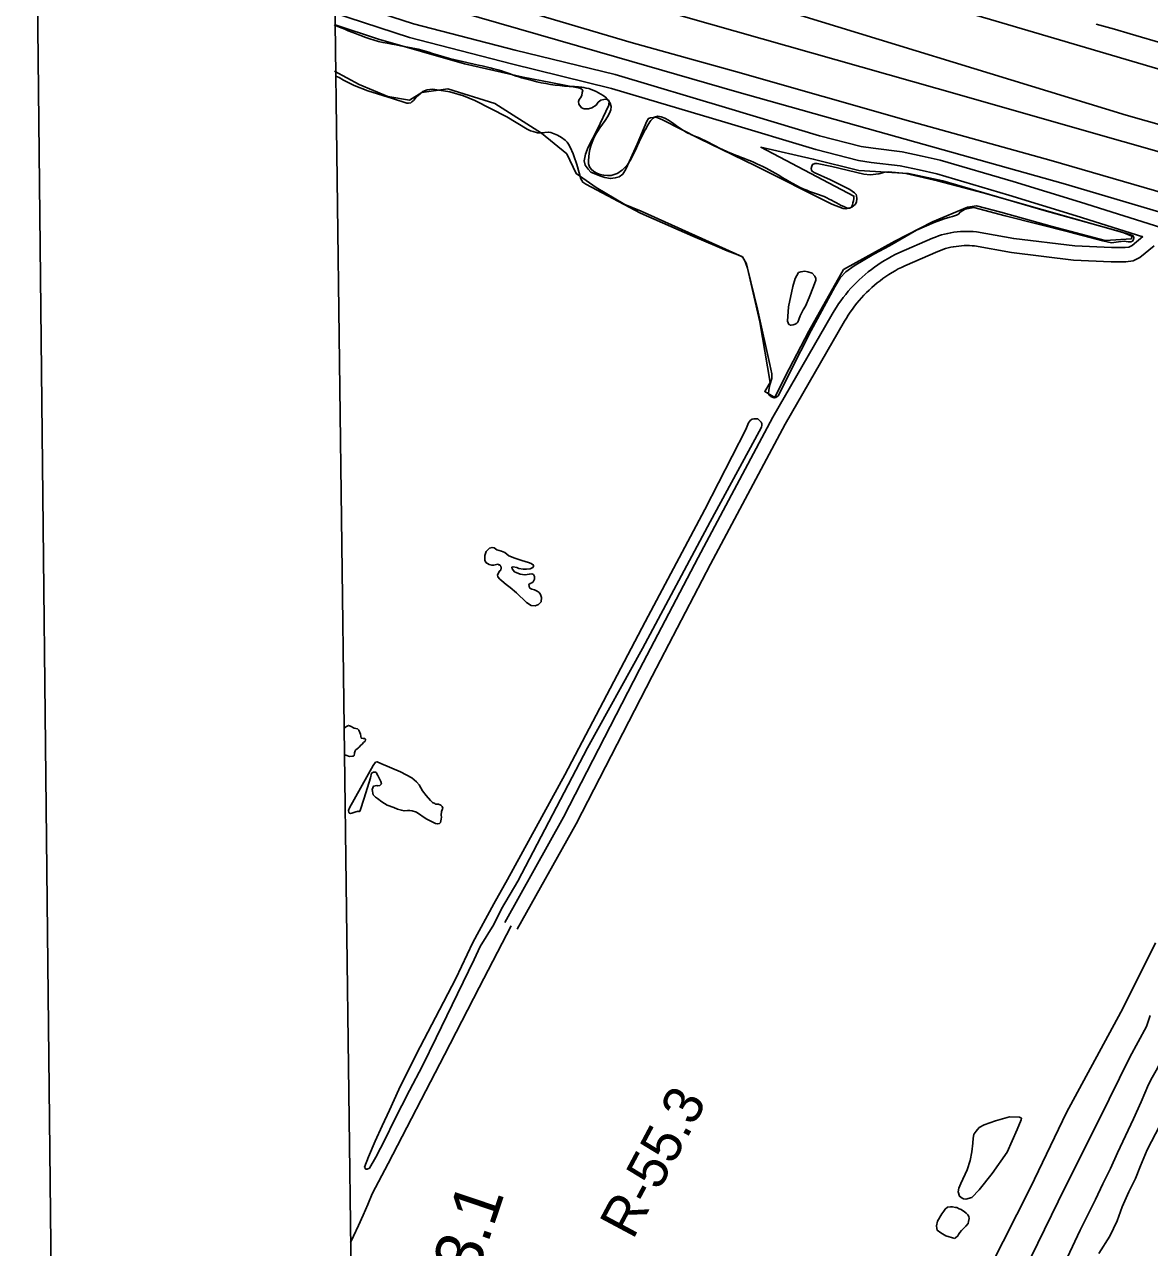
# Model space of a CAD drawing. Extents: x 3734862 to 3772949, y 391520 to 417239.
# Drawn here: x 3738202 to 3740576, y 410402 to 412981 of the extents above; entities that cross this region are included whole.
import ezdxf

# ---------------------------------------------------------------- set-up
doc = ezdxf.new("R2010")
doc.units = 0
for name, color, linetype in [('V-ANNO-SYMB', 7, 'Continuous'), ('V-GRID-FRAM', 7, 'Continuous'), ('V-LEVE-TOET', 7, 'Continuous'), ('V-RIVR-RANG-IDEN', 7, 'Continuous'), ('V-ROAD-CNTR', 7, 'Continuous'), ('V-SITE-VEGE', 7, 'Continuous'), ('V-SURV-IDEN', 7, 'Continuous'), ('V-TOPO-SHOR', 7, 'Continuous'), ('V-WETL-SWMP', 7, 'Continuous')]:
    doc.layers.add(name, color=color, linetype=linetype)

msp = doc.modelspace()

# ---------------------------------------------------------------- linework, layer by layer
at = {"layer": 'V-ANNO-SYMB'}
msp.add_lwpolyline([(3738444.4, 392757.5), (3771525.7, 393106.9), (3771283.7, 416022.2), (3738202.3, 415672.8), (3738444.4, 392757.5)], dxfattribs=at)
at = {"layer": 'V-GRID-FRAM'}
msp.add_lwpolyline([(3738832.3, 415033.8), (3770599.2, 415447.4), (3770843.8, 397266.6), (3739061.1, 396852.8), (3738832.3, 415033.8)], dxfattribs=at)
at = {"layer": 'V-LEVE-TOET'}
for points in [[(3738852.9, 413396.4), (3739138.4, 413315.6), (3740264.7, 412984.9), (3741306.9, 412677.6), (3741416.7, 412646.4), (3741439.2, 412637.7), (3741731.3, 412522.7), (3742578.6, 412200.2), (3743221.3, 411958.2), (3743367.5, 411908.1)], [(3744926.8, 411188.3), (3744890.4, 411207.3), (3744850.8, 411205.9), (3744810.7, 411224.9), (3744044.1, 411535), (3743485.6, 411757.3), (3743467, 411746.5), (3743430.2, 411739.8), (3743419.1, 411736.3), (3743236.4, 411801.8), (3743192.8, 411831.9), (3743145.7, 411873.1), (3742641.7, 412061.3), (3741586.5, 412475.4), (3741466, 412517.8), (3741404.7, 412536.6), (3741298.7, 412571.4), (3740527, 412789.8), (3739719, 413038.2), (3738899.6, 413268.3), (3738854.4, 413281.1)]]:
    msp.add_lwpolyline(points, dxfattribs=at)
at = {"layer": 'V-ROAD-CNTR'}
for points in [[(3738852, 413216.3), (3739597.6, 412997), (3740128.2, 412846.1), (3740911.5, 412622.8), (3741371.7, 412476), (3742051.4, 412232), (3742605.7, 412017.1), (3743130.7, 411814.9), (3743608.3, 411634.1), (3744107.4, 411440.8)], [(3738862.3, 413035.2), (3739023, 412982.8), (3739237.4, 412927.1), (3739448.5, 412875.5), (3739688.3, 412804.2), (3739880, 412746.4), (3739967.9, 412724.2), (3739993.1, 412720.2), (3740054.5, 412712.6), (3740096.2, 412703.8), (3740134.5, 412695.2), (3740288, 412650), (3740430.4, 412606.5), (3740613.5, 412548.9), (3740830.5, 412486.5), (3741011.5, 412434), (3741254.2, 412360.8), (3741297.7, 412344.9), (3741301, 412343.4), (3741304.5, 412341.7), (3741307.8, 412339.7), (3741310.9, 412337.4), (3741314.4, 412334.5), (3741315.1, 412333.7)], [(3738853, 413006.7), (3739014.6, 412954), (3739230.1, 412898), (3739440.6, 412846.5), (3739679.7, 412775.4), (3739872, 412717.5), (3739961.9, 412694.8), (3739988.9, 412690.5), (3740049.6, 412683), (3740089.8, 412674.5), (3740127, 412666.1), (3740279.4, 412621.3), (3740421.6, 412577.9), (3740562, 412533.7)], [(3739215.9, 411087.9), (3739339.5, 411310), (3739500.1, 411621.1), (3739623.6, 411857), (3739781.4, 412153.3), (3739906.6, 412370.7), (3739910.8, 412377.8), (3739915.3, 412385), (3739920, 412392), (3739924.8, 412398.8), (3739929.9, 412405.6), (3739935.1, 412412.2), (3739940.5, 412418.7), (3739946, 412425), (3739951.7, 412431.2), (3739957.6, 412437.2), (3739963.7, 412443.1), (3739969.9, 412448.8), (3739976.2, 412454.3), (3739982.7, 412459.7), (3739989.4, 412464.9), (3739996.1, 412469.9), (3740003, 412474.7), (3740010.1, 412479.4), (3740017.2, 412483.8), (3740024.5, 412488.1), (3740031.9, 412492.2), (3740039.3, 412496), (3740047, 412499.8), (3740118.1, 412530.6), (3740124.4, 412533.1), (3740130.7, 412535.3), (3740137.2, 412537.4), (3740143.7, 412539.2), (3740150.2, 412540.7), (3740156.8, 412542), (3740163.5, 412543.1), (3740170.2, 412544), (3740176.9, 412544.6), (3740183.6, 412545), (3740190.4, 412545.1), (3740197.1, 412545), (3740203.8, 412544.6), (3740210.9, 412544), (3740289.6, 412529.9), (3740418.2, 412514.3), (3740495.8, 412510.7), (3740524.3, 412510.7), (3740532.4, 412511.9), (3740539.1, 412515.4), (3740562.2, 412534.5)], [(3739242.2, 411073.3), (3739366, 411295.8), (3739526.7, 411607.3), (3739650.1, 411843), (3739807.6, 412138.7), (3739932.5, 412355.5), (3739936.4, 412362.2), (3739940.5, 412368.6), (3739944.7, 412375), (3739949.1, 412381.2), (3739953.7, 412387.3), (3739958.4, 412393.3), (3739963.3, 412399.2), (3739968.3, 412404.9), (3739973.5, 412410.5), (3739978.8, 412416), (3739984.3, 412421.3), (3739989.9, 412426.4), (3739995.7, 412431.5), (3740001.5, 412436.3), (3740007.5, 412441), (3740013.7, 412445.6), (3740019.9, 412449.9), (3740026.3, 412454.1), (3740032.8, 412458.2), (3740039.3, 412462), (3740046, 412465.7), (3740052.8, 412469.2), (3740059.5, 412472.5), (3740129.6, 412502.9), (3740134.9, 412505), (3740140.2, 412506.9), (3740145.7, 412508.6), (3740151.1, 412510.1), (3740156.6, 412511.4), (3740162.2, 412512.5), (3740167.8, 412513.4), (3740173.4, 412514.1), (3740179, 412514.7), (3740184.7, 412515), (3740190.4, 412515.1), (3740196, 412515), (3740201.7, 412514.7), (3740206.9, 412514.2), (3740285.1, 412500.2), (3740415.8, 412484.4), (3740495.1, 412480.7), (3740526.4, 412480.7), (3740541.7, 412482.9), (3740555.8, 412490.3), (3740585.5, 412514.8)], [(3739229.1, 411080.6), (3739161.9, 410950.9), (3739088.2, 410808.6), (3738969.9, 410579.1), (3738936.1, 410515.8)], [(3740353.1, 410275.8), (3740429.7, 410438.9), (3740446, 410471.3), (3740462, 410503.8), (3740477.8, 410536.4), (3740493.4, 410569.2), (3740508.8, 410602), (3740525.5, 410637.8), (3740542, 410673.8), (3740558.2, 410709.8), (3740574.2, 410745.9), (3740581.8, 410760.9), (3740589.7, 410775.7), (3740597.7, 410790.4), (3740606, 410805), (3740614.5, 410819.5), (3740620.1, 410828.8)], [(3738890.5, 410413), (3738896.6, 410426.2), (3738906.8, 410448.4), (3738916.8, 410470.8), (3738926.6, 410493.3), (3738936.1, 410515.8)]]:
    msp.add_lwpolyline(points, dxfattribs=at)
at = {"layer": 'V-SITE-VEGE'}
msp.add_lwpolyline([(3740469, 410389.8), (3740492.1, 410426.1), (3740507.7, 410458.5), (3740518.6, 410488.4), (3740532.4, 410519.6), (3740546.6, 410547.5), (3740557, 410574.2), (3740570.8, 410608.5), (3740597.9, 410659.6)], dxfattribs=at)
at = {"layer": 'V-TOPO-SHOR'}
for points in [[(3738856.3, 413130.5), (3738965.1, 413099.9), (3739232.9, 413017.1), (3739482.6, 412943.4), (3739702.8, 412882.3), (3740072.4, 412776.8), (3740368.6, 412694.2), (3740629.8, 412618.9), (3740925.4, 412535.7), (3741148.2, 412471.1), (3741399.8, 412389.3), (3741715.2, 412277.9), (3742012.2, 412157.4), (3742216.5, 412081.7)], [(3738856.9, 413083.7), (3739161.6, 412995.9), (3739452.4, 412912.1), (3739705.5, 412839.6), (3740003.1, 412755.6), (3740393.5, 412645.8), (3740671.5, 412564.1), (3740972.5, 412480.8), (3741257.8, 412388.9), (3741438.8, 412334.5), (3741752.7, 412215.1), (3741995.4, 412125.2), (3742217.9, 412039.1), (3742410.1, 411964.3), (3742754, 411823.4), (3743083.5, 411701.7), (3743238, 411641.7), (3743590.1, 411495.3), (3743868.3, 411385.2), (3744209.8, 411261.9), (3744443, 411170.9), (3744579.1, 411127.5)], [(3738858.2, 412980.3), (3738949.6, 412950.5), (3739131, 412898.4), (3739254.7, 412870.1), (3739313.1, 412858.9), (3739373.8, 412847.1), (3739378.4, 412844.7), (3739380.3, 412841.8), (3739379.3, 412837.6), (3739378.2, 412831.6), (3739375.8, 412826.9), (3739372.4, 412822.8), (3739371, 412819), (3739372.3, 412813.4), (3739377.8, 412805.8), (3739383.4, 412803.4), (3739392.7, 412803.7), (3739399.3, 412805.9), (3739408.3, 412810.9), (3739412.6, 412817.4), (3739418.3, 412822), (3739424.9, 412822.8), (3739431, 412823.7), (3739435.7, 412820.3), (3739435.5, 412811), (3739410.3, 412758.9), (3739391.4, 412722.7), (3739386, 412707.8), (3739383, 412693.8), (3739385.2, 412684.8), (3739391.6, 412676.3), (3739397.1, 412669.6), (3739405.5, 412666.2), (3739416.2, 412662.3), (3739426.5, 412658.9), (3739438.6, 412656.3), (3739448.9, 412657.6), (3739456.9, 412659.8), (3739464.5, 412665.7), (3739471.2, 412676.4), (3739495.1, 412728.9), (3739515.1, 412777.3), (3739518.9, 412782.9), (3739523.1, 412784.7), (3739533.5, 412785.9), (3739538.6, 412784.4), (3739548.4, 412780.1), (3739625.5, 412740.9), (3739744.9, 412683.6), (3739905.7, 412602.3), (3739929.5, 412593.5), (3739935.5, 412592.5), (3739944.5, 412594.7), (3739947.8, 412596), (3739954.9, 412602), (3739957.8, 412606.6), (3739958.4, 412614.6), (3739958, 412619.7), (3739957.1, 412622.6), (3739953.9, 412626.4), (3739943.7, 412633.1), (3739902.8, 412653.4), (3739868.4, 412669), (3739864.2, 412671.9), (3739862.8, 412674.2), (3739862.4, 412677.5), (3739863.9, 412682.6), (3739864.9, 412686.4), (3739870.1, 412688.2), (3739874.8, 412688.1), (3739906.1, 412681.5), (3739973.3, 412665.4), (3739986.8, 412664.2), (3740005.1, 412666.7), (3740017.8, 412669.8), (3740025.3, 412670.6), (3740061.8, 412666.8), (3740128.6, 412651.6), (3740225.1, 412626.6), (3740534.7, 412538.6), (3740541.2, 412535.3), (3740542.6, 412531.5)], [(3739952.5, 412619.1), (3739952.4, 412619.4), (3739756.2, 412722.4), (3739866.6, 412697.6), (3739962.5, 412673.7), (3740067.7, 412667), (3740139.6, 412651.3), (3740353.5, 412588.8), (3740518.4, 412543.2), (3740538.9, 412535.1), (3740537.8, 412529.4), (3740482.2, 412526.1), (3740370.9, 412555.4), (3740262.6, 412585.4), (3740210.8, 412598.7), (3740192.3, 412596.1), (3740118.4, 412565), (3740038.4, 412524.2), (3739930.3, 412464.3), (3739857.2, 412334.3), (3739807.1, 412239.3), (3739785.2, 412194.8), (3739764.3, 412207.3), (3739775.3, 412226.4), (3739753.9, 412354.4), (3739725.8, 412476.6), (3739717, 412491.6), (3739503.5, 412587.8), (3739468.8, 412602), (3739408.2, 412637.8), (3739366.1, 412666.8), (3739346.5, 412708.8), (3739293.2, 412752.1), (3739194.4, 412814.7), (3739095.9, 412845.9), (3739040.9, 412837.8), (3739014.9, 412821.5), (3738969, 412829.5), (3738908.4, 412855.1), (3738856.8, 412882.9)], [(3738866.3, 412869.4), (3738859.5, 412872.4)], [(3740542.6, 412531.5), (3740542.1, 412527.8), (3740540.1, 412524.5), (3740536.8, 412523.2), (3740534, 412523.2), (3740531.2, 412523.2), (3740522.3, 412524.3), (3740510.6, 412523.1), (3740496, 412521), (3740477.4, 412525.1), (3740407.9, 412543.1), (3740271.6, 412578.1), (3740205.4, 412595.1), (3740194.1, 412593.4), (3740187.1, 412592.1), (3740182.4, 412589.4), (3740176.7, 412585.2), (3740172.8, 412581.1), (3740169.1, 412579.3), (3740160.6, 412576.6), (3740155, 412575.3), (3740142.7, 412571.7), (3740121.5, 412563.7), (3740084.7, 412547.4), (3740027.5, 412514.6), (3739994.4, 412497.3), (3739953.2, 412472.7), (3739935.2, 412459.4), (3739923.3, 412447.4), (3739912.2, 412427.9), (3739862, 412336), (3739818, 412249.1), (3739797.6, 412207.3), (3739792.3, 412198.5), (3739789.9, 412196.2), (3739788.5, 412194.8), (3739784.7, 412193.9), (3739783.8, 412193.9), (3739778.2, 412196.4), (3739777.3, 412196.9), (3739777.3, 412197.3), (3739773.6, 412199.7), (3739772.2, 412203.5), (3739772.8, 412210.5), (3739774.9, 412221.3), (3739775.9, 412223.6), (3739779.3, 412234.8), (3739779, 412244.6), (3739775.1, 412264.3), (3739748.9, 412381), (3739727.8, 412467.5), (3739723.8, 412479.7), (3739719.7, 412487.8), (3739715.1, 412492.1), (3739707.2, 412495.9), (3739684.9, 412504.3), (3739663.5, 412513), (3739612.8, 412535), (3739502, 412583.1), (3739386.4, 412644.5), (3739380.4, 412648.8), (3739376.3, 412655.5), (3739372.7, 412668.6), (3739367.9, 412686), (3739361.6, 412704), (3739359.8, 412708.7), (3739353.9, 412722.3), (3739350.3, 412729), (3739347.6, 412733.2), (3739343.4, 412737.5), (3739335.5, 412742.8), (3739326.7, 412747.6), (3739313.2, 412753.5), (3739307.6, 412754.5), (3739293.5, 412752.8), (3739284.6, 412752.5), (3739275.3, 412755.5), (3739269.7, 412757), (3739262.8, 412760.8), (3739220.1, 412786.8), (3739152.7, 412820.7), (3739128.5, 412831), (3739100.1, 412839.4), (3739077.6, 412843), (3739063.2, 412844.7), (3739051.9, 412843.5), (3739042.5, 412840.3), (3739032, 412830.7), (3739027.7, 412826), (3739023, 412821), (3739019.6, 412818.2), (3739017.3, 412816.4), (3739012.6, 412815.5), (3739009.3, 412815.6), (3738978.5, 412825.4), (3738926.8, 412841.7), (3738897.9, 412852.5), (3738875.1, 412863.7), (3738866.3, 412869.4)], [(3739812.5, 412355.6), (3739814.4, 412386), (3739823.5, 412428.8), (3739828.5, 412445.5), (3739835.7, 412458), (3739840.4, 412459.8), (3739848.8, 412461.1), (3739855.3, 412460), (3739864.1, 412456.6), (3739869.7, 412450.5), (3739871.9, 412445.8), (3739871.9, 412442), (3739867.4, 412429), (3739857.7, 412405.8), (3739849.9, 412387.2), (3739845.1, 412379.4), (3739838.9, 412366.9), (3739836.4, 412359.4), (3739834, 412353.9), (3739832.1, 412351.6), (3739828.3, 412349.3), (3739824.1, 412348), (3739819.8, 412347.6), (3739817.5, 412347.6), (3739816.1, 412348.6), (3739815.2, 412349), (3739813.8, 412351.9), (3739812.5, 412355.6)], [(3739221.5, 411178.6), (3739342.2, 411398.7), (3739511.9, 411722), (3739638, 411958.8), (3739724.1, 412127), (3739730, 412141.4), (3739734.3, 412147), (3739737.6, 412149.3), (3739741.4, 412149.7), (3739749.3, 412149.5)], [(3739243.6, 411175.1), (3739390.2, 411456.2), (3739506.5, 411665.5), (3739649, 411932.6), (3739752.4, 412123), (3739757.2, 412132.3), (3739758.2, 412136.5), (3739758.3, 412139.7), (3739756.5, 412143), (3739749.3, 412149.5)], [(3739201.4, 411843.2), (3739192.5, 411841), (3739188.2, 411841), (3739182.6, 411842.5), (3739175.7, 411846.9), (3739173.9, 411851.6), (3739173.6, 411861.9), (3739176.5, 411869.8), (3739183.7, 411876.7), (3739188.8, 411878.5), (3739193.5, 411878), (3739199.1, 411873.7), (3739208.9, 411870.7), (3739215.8, 411867.8), (3739224.2, 411861.1), (3739237.2, 411856.2), (3739251.6, 411850.8), (3739265.6, 411846.8), (3739271.7, 411844.4), (3739276.3, 411841.5), (3739276.3, 411838.7), (3739274.8, 411835.9), (3739269.2, 411833.6), (3739261.6, 411832.8), (3739254.6, 411832.9), (3739245.7, 411834), (3739241.1, 411836), (3739233.2, 411838), (3739230.8, 411837.1), (3739231.2, 411833.3), (3739236.3, 411827.1), (3739248.4, 411822.3), (3739258.2, 411820.7), (3739267.6, 411822.4), (3739272.7, 411822.8), (3739276, 411821.3), (3739278.7, 411817.1), (3739278.2, 411811.5), (3739275.7, 411806.3), (3739272.9, 411804.1), (3739269.1, 411802.7), (3739266.7, 411800.4), (3739267.6, 411793.4), (3739268.5, 411792.4), (3739269.9, 411791.9), (3739272.7, 411790.9), (3739278.7, 411789), (3739284.3, 411786.5), (3739288, 411783.2), (3739291.2, 411779.4), (3739293.5, 411772.8), (3739292.4, 411763.9), (3739287.1, 411758.4), (3739280.1, 411755.7), (3739271.2, 411756.3), (3739261.4, 411762.5), (3739240.7, 411782.6), (3739227.3, 411794), (3739218.5, 411800.3), (3739209.2, 411807.9), (3739205.1, 411811.7), (3739201.4, 411816.9), (3739200.6, 411820.7), (3739204.9, 411828.6), (3739207.3, 411830.9), (3739208.3, 411835.6), (3739207.4, 411838.9), (3739206, 411840.7), (3739205.1, 411842.2), (3739203.2, 411842.2), (3739201.4, 411843.2)], [(3738876.8, 411496.3), (3738877.7, 411498), (3738881.5, 411501.3), (3738885.7, 411503.1), (3738889.9, 411501.6), (3738897.8, 411497.7), (3738904.8, 411496.2), (3738907.6, 411493.3), (3738911.2, 411484.8), (3738912.9, 411476.4), (3738917.1, 411475.4), (3738919.9, 411475.8), (3738921.8, 411473.9), (3738922.2, 411472.5), (3738921.2, 411470.2), (3738917.5, 411466.9), (3738914.6, 411463.7), (3738911.7, 411461.4), (3738908.4, 411457.2), (3738907, 411456.3), (3738905.1, 411454.5), (3738900.8, 411451.3), (3738899.8, 411449.9), (3738898.8, 411445.2), (3738898.8, 411444.3), (3738897.8, 411440.1), (3738896.8, 411438.7), (3738894.5, 411438.3)], [(3738894.5, 411438.3), (3738887.9, 411437.9), (3738880.5, 411440.4), (3738877.5, 411441.4)], [(3738981.3, 411330), (3738967.8, 411335), (3738956.6, 411342.2), (3738947.4, 411348.9), (3738942.8, 411352.2), (3738938.1, 411357), (3738936, 411368.3), (3738938.4, 411374.8), (3738945.5, 411376.5), (3738947.8, 411376), (3738952, 411376.4), (3738955.4, 411380.1), (3738954.5, 411385.3), (3738950.4, 411391.9), (3738948.2, 411397.6), (3738944.5, 411403.7), (3738942.7, 411404.7), (3738938.9, 411404.8), (3738934.7, 411402.5), (3738932.6, 411392.7), (3738918.8, 411349.8), (3738910.4, 411323.7), (3738909.5, 411321.8), (3738908.1, 411321.9), (3738906.2, 411322.4), (3738899.1, 411320.6), (3738893, 411317.9), (3738890.2, 411317.5), (3738887.8, 411318), (3738886.9, 411319.9), (3738886.1, 411324.1), (3738888, 411329.2), (3738937.7, 411418.4), (3738943, 411425.8), (3738946.3, 411426.7), (3738954.2, 411423.2), (3738995.6, 411405.2), (3739019.3, 411392.7), (3739029.5, 411384.5), (3739035, 411377.9), (3739042.3, 411365.1), (3739050.1, 411355.2), (3739059.3, 411345.2), (3739063.4, 411340.9), (3739068.5, 411338.5), (3739069.9, 411337.5), (3739076, 411337.4), (3739081.1, 411335.4), (3739082.5, 411334), (3739083.9, 411332.1), (3739084.8, 411328.4), (3739082.3, 411321.4), (3739081.7, 411313.9), (3739082.1, 411310.1), (3739081.6, 411305.9), (3739080.1, 411298.5), (3739078.2, 411296.6), (3739073.9, 411295.7), (3739069.7, 411296.7), (3739049.8, 411306.4), (3739029.4, 411320.4), (3739020.5, 411323.3), (3739015.4, 411323.9), (3739010.2, 411323.5), (3739003.2, 411323.1), (3738997.6, 411324.2), (3738989.6, 411326.6), (3738981.3, 411330)], [(3738919.9, 410571.5), (3738928.5, 410593.3), (3738942, 410626.7), (3738957.1, 410658.6), (3738972.2, 410691.8), (3738992.4, 410735.7), (3739029.5, 410811), (3739069.5, 410887.2), (3739112.8, 410969.9), (3739148.3, 411045.3), (3739192.5, 411126.7), (3739221.5, 411178.6)], [(3738919.9, 410571.5), (3738922.5, 410567.7), (3738925.3, 410567.4), (3738930, 410569.7), (3738943.7, 410593.1), (3738963.3, 410630.7), (3738982.5, 410670.2), (3739015, 410733.1), (3739042.2, 410785.5), (3739070.9, 410844.6), (3739115.7, 410937.5), (3739150.9, 411009.6), (3739163.8, 411037.2), (3739192.4, 411083.3), (3739208.8, 411116.5), (3739243.6, 411175.1)], [(3740238.3, 410357.8), (3740324.8, 410528.8), (3740400.9, 410686.8), (3740515.6, 410898.7), (3740560.1, 410986.1), (3740588.8, 411044.5)], [(3740577.7, 410891.8), (3740574.2, 410881.2), (3740569.4, 410868.2), (3740534.6, 410803.6), (3740469.2, 410670.5), (3740397.5, 410527.9), (3740326.4, 410382.6)], [(3740180.4, 410506.3), (3740175, 410510.5), (3740172.4, 410519.4), (3740174, 410527.6), (3740177.9, 410537.6), (3740191.2, 410566.2), (3740197.8, 410585.9), (3740201, 410604.1), (3740203.4, 410622.6), (3740203.8, 410633.1), (3740205.4, 410640.8), (3740205.8, 410642), (3740210.1, 410647.3), (3740216.7, 410655.4), (3740227.2, 410660.8), (3740251.2, 410669.6), (3740280.3, 410678), (3740301.5, 410677.1), (3740305.8, 410674.8), (3740305.4, 410671.3), (3740296.8, 410650.8), (3740275.7, 410603.3), (3740243.7, 410558.6), (3740216.5, 410523.9), (3740201.3, 410507.7), (3740188.6, 410504.3), (3740183.9, 410504.7), (3740180.4, 410506.3)], [(3740165, 410421.2), (3740146.4, 410427.1), (3740136, 410433.3), (3740128.3, 410438.8), (3740127.1, 410442.3), (3740126.4, 410448.1), (3740128.8, 410457.7), (3740137.7, 410473.2), (3740142.4, 410479), (3740145.1, 410483.2), (3740149.8, 410487.4), (3740156, 410488.2), (3740160.2, 410487.8), (3740166.8, 410486.6), (3740169.5, 410486.6), (3740174.1, 410484.2), (3740178.8, 410482.3), (3740181.5, 410480.3), (3740185.3, 410478), (3740189.2, 410474.5), (3740192.7, 410471.4), (3740194.6, 410467.9), (3740195.7, 410463.6), (3740194.1, 410457.4), (3740193.4, 410453.2), (3740188.3, 410447.4), (3740184.8, 410443.6), (3740179.4, 410438.5), (3740175.9, 410433.9), (3740173.1, 410429.7), (3740171.6, 410426.6), (3740166.9, 410422.7), (3740165, 410421.2)]]:
    msp.add_lwpolyline(points, dxfattribs=at)
msp.add_spline([(3738855.7, 412980.4), (3738915.5, 412956.4), (3738922.4, 412953.8), (3738995.9, 412936.5), (3739055.3, 412922.8), (3739063.3, 412920.1), (3739160, 412895.8), (3739224.8, 412877.9), (3739228.8, 412876.4), (3739273.6, 412862.9), (3739351.5, 412850.8), (3739382.4, 412848.4), (3739423.3, 412831.3), (3739438.2, 412815.5), (3739411, 412755.4), (3739392.3, 412694.4), (3739392.3, 412687.3), (3739440, 412663.2), (3739469.5, 412680.3), (3739502.9, 412741.8), (3739513.7, 412762.1), (3739531.7, 412785.7), (3739594.7, 412756.4), (3739624.1, 412742.8), (3739684, 412713.6), (3739734, 412693.6), (3739786.1, 412667.8), (3739846.9, 412634.2), (3739895.1, 412615.7), (3739936.7, 412595), (3739941.1, 412593.7), (3739952.5, 412619.1)], degree=3, dxfattribs=at)
at = {"layer": 'V-WETL-SWMP'}
for p, q in [((3740463.3, 412982.3), (3740502, 412971.7)), ((3740502, 412971.7), (3740535.1, 412961.4)), ((3740535.1, 412961.4), (3740611.7, 412939.4))]:
    msp.add_line(p, q, dxfattribs=at)

# ---------------------------------------------------------------- texts
at = {"layer": 'V-RIVR-RANG-IDEN'}
msp.add_text('R-55.3', height=83, rotation=61.9009, dxfattribs=at).set_placement((3739485.9, 410416.9))
at = {"layer": 'V-SURV-IDEN'}
msp.add_text('1354+13.1', height=100, rotation=71.3758, dxfattribs=at).set_placement((3739012.2, 409912.1))

doc.saveas('drawing.dxf')
